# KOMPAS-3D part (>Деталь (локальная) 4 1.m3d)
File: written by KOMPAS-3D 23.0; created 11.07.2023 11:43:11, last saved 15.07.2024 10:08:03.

Document properties: Автор: Владимир; Полное имя файла: C:\Users\YNA_NN\AppData\Local\Temp\KOMPAS-3D\ktf8-bd45-7a8d-d203\_Деталь (локальная) 4 1.m3d

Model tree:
1. Эскиз:2  (with: Элемент выдавливания:2)
2. Элемент выдавливания:6  (labels: Сталь 3сп ГОСТ 380-2005)
     Расстояние 1 = 10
